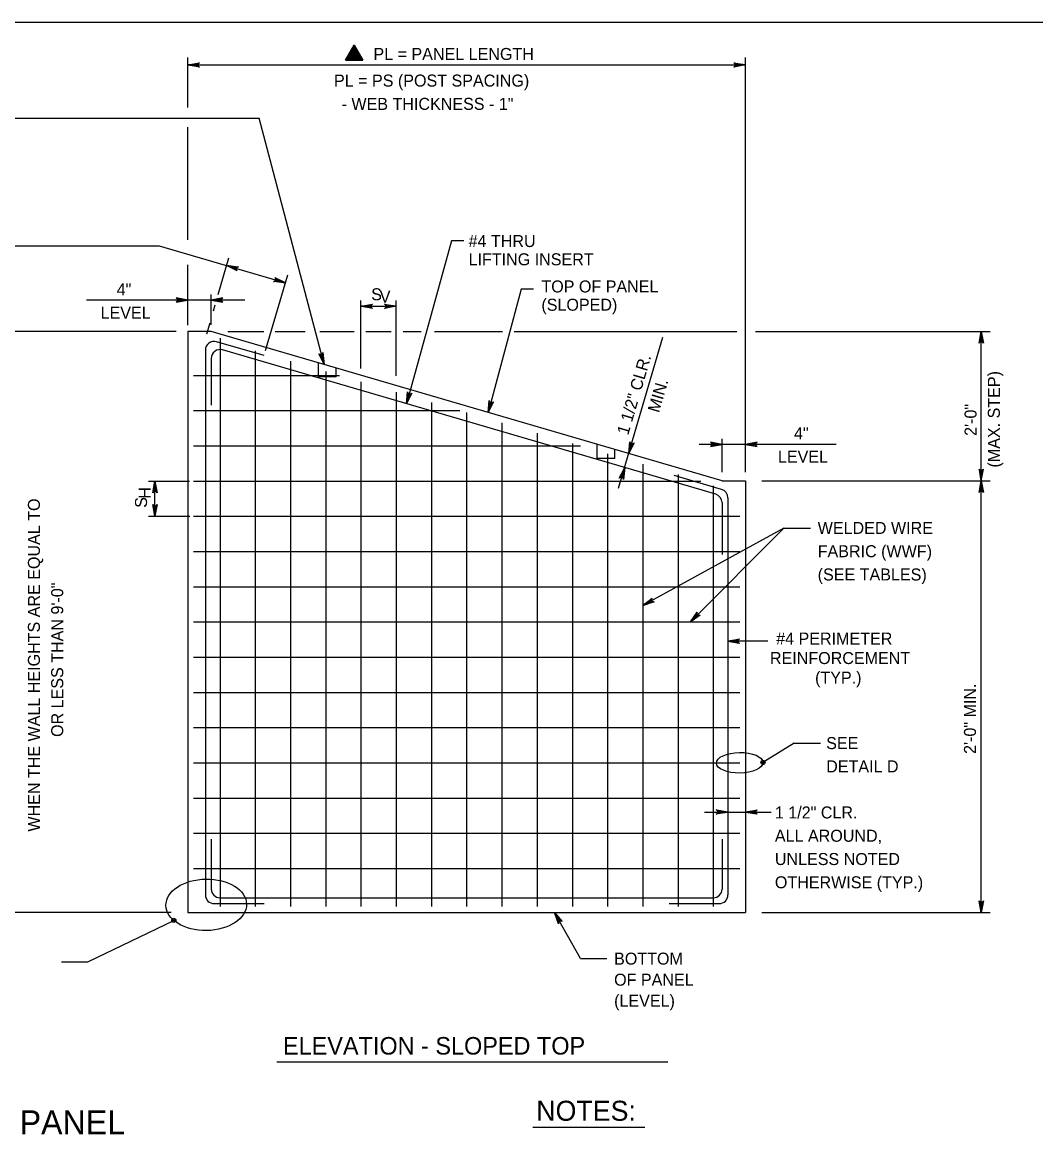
# Model space of a CAD drawing. Extents: x 3761 to 5458, y -616 to 1166.
# Drawn here: x 4072.9 to 4331.8, y -321.6 to -37.3 of the extents above; entities that cross this region are included whole.
import ezdxf

# ---------------------------------------------------------------- set-up
doc = ezdxf.new("R2010")
doc.units = 0
doc.layers.add('1', color=7, linetype='Continuous')
doc.layers.add('2', color=7, linetype='Continuous')

msp = doc.modelspace()

# ---------------------------------------------------------------- linework, layer by layer
at = {"layer": '1'}
for p, q in [((4115.21, -59.07), (4115.21, -46.32)), ((4115.21, -48.22), (4257.71, -48.22)), ((4157.71, -45.74), (4157.71, -45.74)), ((4257.71, -152.33), (4257.71, -46.32)), ((3958.96, -61.84), (4133.46, -61.84)), ((4150.03, -124.76), (4133.46, -61.84)), ((4115.21, -92.92), (4115.21, -64.09)), ((4182.57, -93.18), (4171.13, -134.83)), ((4185.7, -93.18), (4182.57, -93.18)), ((3961.02, -94.44), (4107.86, -94.44)), ((4107.86, -94.44), (4140.16, -103.89)), ((4115.21, -114.74), (4115.21, -99.31)), ((4122.99, -106.92), (4125.74, -97.51)), ((4135.09, -121.22), (4140.74, -101.9)), ((4121.21, -114.61), (4121.21, -106.91)), ((4200.4, -105.5), (4191.97, -137.02)), ((4203.54, -105.5), (4200.4, -105.5)), ((4129.81, -108.31), (4089.32, -108.31)), ((4121.78, -111.04), (4122.22, -109.54)), ((4159.46, -125.78), (4159.46, -108.43)), ((4159.46, -109.9), (4168.46, -109.9)), ((4168.46, -127.71), (4168.46, -108.43)), ((4112.25, -116.32), (3985.19, -116.32)), ((4115.21, -116.32), (4115.21, -264.82)), ((4121.21, -116.32), (4115.21, -116.32)), ((4120.06, -116.92), (4120.89, -114.09)), ((4251.71, -154.5), (4121.21, -116.32)), ((4125.45, -116.32), (4134.66, -116.32)), ((4137.51, -116.32), (4145.24, -116.32)), ((4148.92, -116.32), (4157.7, -116.32)), ((4160.74, -116.32), (4167.17, -116.32)), ((4170.22, -116.32), (4174.81, -116.32)), ((4178.21, -116.32), (4195.63, -116.32)), ((4198.61, -116.32), (4255.48, -116.32)), ((4260.22, -116.32), (4320.16, -116.32)), ((4317.91, -264.82), (4317.91, -116.32)), ((4134.71, -122.51), (4122.58, -118.96)), ((4123.46, -118.08), (4123.46, -263.33)), ((4225.29, -156.39), (4236.59, -117.76)), ((4119.71, -121.11), (4119.71, -260.32)), ((4250.1, -157.93), (4124.08, -121.06)), ((4132.46, -121.28), (4132.46, -263.33)), ((4121.21, -123.21), (4121.21, -135.19)), ((4141.46, -123.92), (4141.46, -263.33)), ((4148.59, -127.97), (4148.59, -124.33)), ((4116.71, -127.57), (4153.97, -127.57)), ((4150.46, -126.55), (4150.46, -263.33)), ((4153.09, -127.97), (4153.09, -125.65)), ((4153.09, -127.97), (4148.59, -127.97)), ((4159.46, -129.18), (4159.46, -263.33)), ((4168.46, -131.81), (4168.46, -263.33)), ((4177.46, -134.45), (4177.46, -263.33)), ((4116.71, -136.57), (4184.74, -136.57)), ((4186.46, -137.08), (4186.46, -263.33)), ((4195.46, -139.71), (4195.46, -263.33)), ((4204.46, -142.34), (4204.46, -263.33)), ((4213.46, -144.98), (4213.46, -263.33)), ((4251.71, -152.33), (4251.71, -143.8)), ((4116.71, -145.57), (4215.51, -145.57)), ((4219.84, -148.81), (4219.84, -145.17)), ((4222.46, -147.61), (4222.46, -263.33)), ((4224.34, -148.81), (4224.34, -146.49)), ((4280.84, -145.21), (4245.83, -145.21)), ((4224.34, -148.81), (4219.84, -148.81)), ((4231.46, -150.24), (4231.46, -263.33)), ((4251.6, -156.7), (4239.47, -153.15)), ((4240.46, -152.87), (4240.46, -263.33)), ((4105.18, -154.57), (4115.62, -154.57)), ((4106.82, -163.57), (4106.82, -154.57)), ((4116.71, -154.57), (4246.28, -154.57)), ((4249.46, -155.75), (4249.46, -263.33)), ((4251.71, -154.5), (4257.71, -154.5)), ((4257.71, -154.5), (4257.71, -264.82)), ((4261.91, -154.5), (4320.16, -154.5)), ((4253.21, -158.85), (4253.21, -260.32)), ((4251.71, -160.08), (4251.71, -173.36)), ((4105.18, -163.57), (4115.7, -163.57)), ((4116.71, -163.57), (4256.21, -163.57)), ((4267.53, -166.62), (4231.46, -186.38)), ((4267.53, -166.62), (4243.61, -190.57)), ((4267.53, -166.62), (4274.26, -166.62)), ((4116.71, -172.57), (4256.21, -172.57)), ((4116.71, -181.57), (4256.21, -181.57)), ((4116.71, -190.57), (4256.21, -190.57)), ((4263.39, -195.48), (4253.21, -195.48)), ((4116.71, -199.57), (4256.21, -199.57)), ((4116.71, -208.57), (4256.21, -208.57)), ((4116.71, -217.57), (4256.21, -217.57)), ((4270.13, -221.56), (4262.15, -226.48)), ((4270.13, -221.56), (4276.87, -221.56)), ((4116.71, -226.57), (4256.21, -226.57)), ((4116.71, -235.57), (4256.21, -235.57)), ((4247.19, -239.15), (4264.24, -239.15)), ((4116.71, -244.57), (4256.21, -244.57)), ((4121.21, -246.08), (4121.21, -258.83)), ((4251.71, -246.08), (4251.71, -258.83)), ((4116.71, -253.57), (4256.21, -253.57)), ((4123.46, -261.08), (4249.46, -261.08)), ((4121.96, -262.57), (4134.71, -262.57)), ((4238.21, -262.57), (4250.96, -262.57)), ((4110.98, -264.82), (3986.76, -264.82)), ((4089.65, -277.4), (4111.63, -266.84)), ((4115.21, -264.82), (4257.71, -264.82)), ((4215.52, -276.61), (4208.91, -264.82)), ((4261.91, -264.82), (4320.16, -264.82)), ((4082.92, -277.4), (4089.65, -277.4)), ((4215.52, -276.61), (4222.25, -276.61)), ((4137.92, -302.99), (4237.83, -302.99)), ((4203.39, -319.69), (4231.96, -319.69))]:
    msp.add_line(p, q, dxfattribs=at)
for points in [[(4155.48, -47.03), (4159.94, -47.03), (4157.71, -43.17), (4155.48, -47.03)], [(4155.48, -47.03), (4157.71, -43.17), (4159.94, -47.03), (4155.48, -47.03), (4157.7, -43.28), (4159.87, -46.98), (4155.56, -46.99), (4157.71, -43.39), (4159.78, -46.92), (4155.67, -46.94), (4157.72, -43.51), (4159.68, -46.85), (4155.77, -46.88), (4157.71, -43.62), (4159.58, -46.8), (4155.88, -46.81), (4157.72, -43.76), (4159.47, -46.75), (4156, -46.75), (4157.71, -43.9), (4159.37, -46.68), (4156.1, -46.69), (4157.71, -44.03), (4159.26, -46.61), (4156.21, -46.62), (4157.71, -44.16), (4159.14, -46.54), (4156.31, -46.56), (4157.72, -44.28), (4159, -46.48), (4156.43, -46.5), (4157.72, -44.41), (4158.87, -46.4), (4156.55, -46.44), (4157.72, -44.56), (4158.75, -46.32), (4156.66, -46.37), (4157.72, -44.69), (4158.63, -46.25), (4156.8, -46.3), (4157.72, -44.82), (4158.52, -46.19), (4156.93, -46.24), (4157.72, -44.97), (4158.39, -46.12), (4157.07, -46.17), (4157.72, -45.1), (4158.26, -46.04), (4157.17, -46.11), (4157.71, -45.23), (4158.13, -45.97), (4157.3, -46.05), (4157.71, -45.36), (4158.03, -45.93), (4157.4, -45.99), (4157.71, -45.48), (4157.93, -45.87), (4157.51, -45.93), (4157.72, -45.61), (4157.84, -45.82), (4157.62, -45.85), (4157.71, -45.75), (4159.93, -47.02), (4157.71, -45.75), (4157.71, -43.19), (4157.72, -45.76), (4155.48, -47.02)], [(4115.21, -48.22), (4118.19, -47.66), (4117.96, -47.82), (4117.84, -48.02), (4117.81, -48.22), (4117.84, -48.42), (4117.96, -48.62), (4118.19, -48.78), (4115.21, -48.22), (4117.96, -48.62), (4117.84, -48.42), (4115.21, -48.22), (4117.81, -48.22), (4117.84, -48.02), (4115.21, -48.22), (4117.96, -47.82)], [(4257.71, -48.22), (4254.73, -48.78), (4254.96, -48.62), (4255.08, -48.42), (4255.11, -48.22), (4255.08, -48.02), (4254.96, -47.82), (4254.73, -47.66), (4257.71, -48.22), (4254.96, -47.82), (4255.08, -48.02), (4257.71, -48.22), (4255.11, -48.22), (4255.08, -48.42), (4257.71, -48.22), (4254.96, -48.62)], [(4125.16, -99.5), (4128.18, -99.8), (4128.04, -99.84), (4127.91, -99.89), (4127.83, -99.97), (4127.74, -100.05), (4127.7, -100.14), (4127.65, -100.23), (4127.64, -100.33), (4127.63, -100.43), (4127.66, -100.54), (4127.69, -100.66), (4127.77, -100.76), (4127.86, -100.87), (4125.16, -99.5), (4127.77, -100.76), (4127.69, -100.66), (4125.16, -99.5), (4127.66, -100.54), (4127.63, -100.43), (4125.16, -99.5), (4127.64, -100.33), (4127.65, -100.23), (4125.16, -99.5), (4127.7, -100.14), (4127.74, -100.05), (4125.16, -99.5), (4127.83, -99.97), (4127.91, -99.89), (4125.16, -99.5), (4128.04, -99.84)], [(4140.16, -103.89), (4137.14, -103.59), (4137.27, -103.54), (4137.4, -103.5), (4137.49, -103.42), (4137.57, -103.34), (4137.62, -103.25), (4137.66, -103.16), (4137.67, -103.06), (4137.68, -102.96), (4137.66, -102.84), (4137.63, -102.73), (4137.54, -102.62), (4137.45, -102.51), (4140.16, -103.89), (4137.54, -102.62), (4137.63, -102.73), (4140.16, -103.89), (4137.66, -102.84), (4137.68, -102.96), (4140.16, -103.89), (4137.67, -103.06), (4137.66, -103.16), (4140.16, -103.89), (4137.62, -103.25), (4137.57, -103.34), (4140.16, -103.89), (4137.49, -103.42), (4137.4, -103.5), (4140.16, -103.89), (4137.27, -103.54)], [(4115.21, -108.31), (4112.23, -107.75), (4112.46, -107.91), (4112.58, -108.11), (4112.61, -108.31), (4112.58, -108.51), (4112.46, -108.71), (4112.23, -108.87), (4115.21, -108.31), (4112.46, -108.71), (4112.58, -108.51), (4115.21, -108.31), (4112.61, -108.31), (4112.58, -108.11), (4115.21, -108.31), (4112.46, -107.91)], [(4121.21, -108.31), (4124.19, -108.87), (4123.96, -108.71), (4123.84, -108.51), (4123.81, -108.31), (4123.84, -108.11), (4123.96, -107.91), (4124.19, -107.75), (4121.21, -108.31), (4123.96, -107.91), (4123.84, -108.11), (4121.21, -108.31), (4123.81, -108.31), (4123.84, -108.51), (4121.21, -108.31), (4123.96, -108.71)], [(4159.46, -109.9), (4162.44, -109.34), (4162.21, -109.5), (4162.09, -109.7), (4162.06, -109.9), (4162.09, -110.1), (4162.21, -110.3), (4162.44, -110.46), (4159.46, -109.9), (4162.21, -110.3), (4162.09, -110.1), (4159.46, -109.9), (4162.06, -109.9), (4162.09, -109.7), (4159.46, -109.9), (4162.21, -109.5)], [(4168.46, -109.9), (4165.48, -110.46), (4165.71, -110.3), (4165.83, -110.1), (4165.86, -109.9), (4165.83, -109.7), (4165.71, -109.5), (4165.48, -109.34), (4168.46, -109.9), (4165.71, -109.5), (4165.83, -109.7), (4168.46, -109.9), (4165.86, -109.9), (4165.83, -110.1), (4168.46, -109.9), (4165.71, -110.3)], [(4317.91, -116.32), (4318.47, -119.31), (4318.31, -119.08), (4318.11, -118.96), (4317.91, -118.92), (4317.71, -118.96), (4317.51, -119.08), (4317.36, -119.31), (4317.91, -116.32), (4317.51, -119.08), (4317.71, -118.96), (4317.91, -116.32), (4317.91, -118.92), (4318.11, -118.96), (4317.91, -116.32), (4318.31, -119.08)], [(4150.03, -124.76), (4148.67, -122.05), (4148.78, -122.14), (4148.88, -122.22), (4149, -122.25), (4149.11, -122.28), (4149.21, -122.27), (4149.31, -122.26), (4149.4, -122.21), (4149.49, -122.17), (4149.57, -122.09), (4149.65, -122), (4149.7, -121.87), (4149.74, -121.74), (4150.03, -124.76), (4149.7, -121.87), (4149.65, -122), (4150.03, -124.76), (4149.57, -122.09), (4149.49, -122.17), (4150.03, -124.76), (4149.4, -122.21), (4149.31, -122.26), (4150.03, -124.76), (4149.21, -122.27), (4149.11, -122.28), (4150.03, -124.76), (4149, -122.25), (4148.88, -122.22), (4150.03, -124.76), (4148.78, -122.14)], [(4171.13, -134.83), (4171.38, -131.8), (4171.47, -132.07), (4171.63, -132.23), (4171.82, -132.32), (4172.02, -132.34), (4172.24, -132.28), (4172.46, -132.1), (4171.13, -134.83), (4172.24, -132.28), (4172.02, -132.34), (4171.13, -134.83), (4171.82, -132.32), (4171.63, -132.23), (4171.13, -134.83), (4171.47, -132.07)], [(4191.97, -137.02), (4192.2, -134), (4192.25, -134.13), (4192.29, -134.26), (4192.37, -134.34), (4192.46, -134.43), (4192.55, -134.47), (4192.64, -134.51), (4192.74, -134.52), (4192.84, -134.53), (4192.95, -134.5), (4193.07, -134.47), (4193.17, -134.38), (4193.28, -134.29), (4191.97, -137.02), (4193.17, -134.38), (4193.07, -134.47), (4191.97, -137.02), (4192.95, -134.5), (4192.84, -134.53), (4191.97, -137.02), (4192.74, -134.52), (4192.64, -134.51), (4191.97, -137.02), (4192.55, -134.47), (4192.46, -134.43), (4191.97, -137.02), (4192.37, -134.34), (4192.29, -134.26), (4191.97, -137.02), (4192.25, -134.13)], [(4227.88, -147.53), (4228.18, -144.51), (4228.27, -144.77), (4228.43, -144.94), (4228.61, -145.03), (4228.81, -145.05), (4229.04, -145), (4229.25, -144.82), (4227.88, -147.53), (4229.04, -145), (4228.81, -145.05), (4227.88, -147.53), (4228.61, -145.03), (4228.43, -144.94), (4227.88, -147.53), (4228.27, -144.77)], [(4251.71, -145.21), (4248.73, -144.65), (4248.96, -144.81), (4249.08, -145.01), (4249.11, -145.21), (4249.08, -145.41), (4248.96, -145.61), (4248.73, -145.77), (4251.71, -145.21), (4248.96, -145.61), (4249.08, -145.41), (4251.71, -145.21), (4249.11, -145.21), (4249.08, -145.01), (4251.71, -145.21), (4248.96, -144.81)], [(4257.71, -145.21), (4260.69, -145.77), (4260.46, -145.61), (4260.34, -145.41), (4260.31, -145.21), (4260.34, -145.01), (4260.46, -144.81), (4260.69, -144.65), (4257.71, -145.21), (4260.46, -144.81), (4260.34, -145.01), (4257.71, -145.21), (4260.31, -145.21), (4260.34, -145.41), (4257.71, -145.21), (4260.46, -145.61)], [(4226.83, -151.12), (4226.53, -154.14), (4226.44, -153.87), (4226.28, -153.7), (4226.1, -153.62), (4225.9, -153.59), (4225.67, -153.65), (4225.45, -153.83), (4226.83, -151.12), (4225.67, -153.65), (4225.9, -153.59), (4226.83, -151.12), (4226.1, -153.62), (4226.28, -153.7), (4226.83, -151.12), (4226.44, -153.87)], [(4317.91, -154.5), (4318.47, -151.51), (4318.31, -151.74), (4318.11, -151.86), (4317.91, -151.9), (4317.71, -151.86), (4317.51, -151.74), (4317.36, -151.51), (4317.91, -154.5), (4317.51, -151.74), (4317.71, -151.86), (4317.91, -154.5), (4317.91, -151.9), (4318.11, -151.86), (4317.91, -154.5), (4318.31, -151.74)], [(4106.82, -154.57), (4107.38, -157.56), (4107.22, -157.33), (4107.02, -157.21), (4106.82, -157.17), (4106.62, -157.21), (4106.42, -157.33), (4106.26, -157.56), (4106.82, -154.57), (4106.42, -157.33), (4106.62, -157.21), (4106.82, -154.57), (4106.82, -157.17), (4107.02, -157.21), (4106.82, -154.57), (4107.22, -157.33)], [(4317.91, -154.5), (4318.47, -157.48), (4318.31, -157.25), (4318.11, -157.13), (4317.91, -157.1), (4317.71, -157.13), (4317.51, -157.25), (4317.36, -157.48), (4317.91, -154.5), (4317.51, -157.25), (4317.71, -157.13), (4317.91, -154.5), (4317.91, -157.1), (4318.11, -157.13), (4317.91, -154.5), (4318.31, -157.25)], [(4106.82, -163.57), (4106.26, -160.59), (4106.42, -160.82), (4106.62, -160.94), (4106.82, -160.97), (4107.02, -160.94), (4107.22, -160.82), (4107.38, -160.59), (4106.82, -163.57), (4107.22, -160.82), (4107.02, -160.94), (4106.82, -163.57), (4106.82, -160.97), (4106.62, -160.94), (4106.82, -163.57), (4106.42, -160.82)], [(4106.82, -163.57), (4106.26, -160.59), (4106.42, -160.82), (4106.62, -160.94), (4106.82, -160.97), (4107.02, -160.94), (4107.22, -160.82), (4107.38, -160.59), (4106.82, -163.57), (4107.22, -160.82), (4107.02, -160.94), (4106.82, -163.57), (4106.82, -160.97), (4106.62, -160.94), (4106.82, -163.57), (4106.42, -160.82)], [(4231.46, -186.38), (4233.81, -184.46), (4233.74, -184.59), (4233.68, -184.71), (4233.68, -184.83), (4233.67, -184.94), (4233.71, -185.04), (4233.74, -185.13), (4233.8, -185.21), (4233.87, -185.29), (4233.97, -185.35), (4234.07, -185.41), (4234.2, -185.43), (4234.34, -185.44), (4231.46, -186.38), (4234.2, -185.43), (4234.07, -185.41), (4231.46, -186.38), (4233.97, -185.35), (4233.87, -185.29), (4231.46, -186.38), (4233.8, -185.21), (4233.74, -185.13), (4231.46, -186.38), (4233.71, -185.04), (4233.67, -184.94), (4231.46, -186.38), (4233.68, -184.83), (4233.68, -184.71), (4231.46, -186.38), (4233.74, -184.59)], [(4243.61, -190.57), (4245.32, -188.07), (4245.29, -188.21), (4245.27, -188.34), (4245.3, -188.46), (4245.33, -188.57), (4245.39, -188.65), (4245.44, -188.73), (4245.53, -188.79), (4245.61, -188.85), (4245.72, -188.88), (4245.84, -188.91), (4245.97, -188.88), (4246.11, -188.86), (4243.61, -190.57), (4245.97, -188.88), (4245.84, -188.91), (4243.61, -190.57), (4245.72, -188.88), (4245.61, -188.85), (4243.61, -190.57), (4245.53, -188.79), (4245.44, -188.73), (4243.61, -190.57), (4245.39, -188.65), (4245.33, -188.57), (4243.61, -190.57), (4245.3, -188.46), (4245.27, -188.34), (4243.61, -190.57), (4245.29, -188.21)], [(4253.21, -195.48), (4256.19, -194.92), (4256.08, -195), (4255.96, -195.08), (4255.9, -195.18), (4255.85, -195.28), (4255.83, -195.38), (4255.81, -195.48), (4255.83, -195.58), (4255.85, -195.68), (4255.9, -195.78), (4255.96, -195.88), (4256.08, -195.96), (4256.19, -196.04), (4253.21, -195.48), (4256.08, -195.96), (4255.96, -195.88), (4253.21, -195.48), (4255.9, -195.78), (4255.85, -195.68), (4253.21, -195.48), (4255.83, -195.58), (4255.81, -195.48), (4253.21, -195.48), (4255.83, -195.38), (4255.85, -195.28), (4253.21, -195.48), (4255.9, -195.18), (4255.96, -195.08), (4253.21, -195.48), (4256.08, -195)], [(4253.21, -239.15), (4250.23, -239.71), (4250.34, -239.63), (4250.46, -239.55), (4250.52, -239.45), (4250.58, -239.35), (4250.59, -239.25), (4250.61, -239.15), (4250.59, -239.05), (4250.58, -238.95), (4250.52, -238.85), (4250.46, -238.75), (4250.34, -238.67), (4250.23, -238.59), (4253.21, -239.15), (4250.34, -238.67), (4250.46, -238.75), (4253.21, -239.15), (4250.52, -238.85), (4250.58, -238.95), (4253.21, -239.15), (4250.59, -239.05), (4250.61, -239.15), (4253.21, -239.15), (4250.59, -239.25), (4250.58, -239.35), (4253.21, -239.15), (4250.52, -239.45), (4250.46, -239.55), (4253.21, -239.15), (4250.34, -239.63)], [(4257.71, -239.15), (4260.69, -238.59), (4260.58, -238.67), (4260.46, -238.75), (4260.4, -238.85), (4260.35, -238.95), (4260.33, -239.05), (4260.31, -239.15), (4260.33, -239.25), (4260.35, -239.35), (4260.4, -239.45), (4260.46, -239.55), (4260.58, -239.63), (4260.69, -239.71), (4257.71, -239.15), (4260.58, -239.63), (4260.46, -239.55), (4257.71, -239.15), (4260.4, -239.45), (4260.35, -239.35), (4257.71, -239.15), (4260.33, -239.25), (4260.31, -239.15), (4257.71, -239.15), (4260.33, -239.05), (4260.35, -238.95), (4257.71, -239.15), (4260.4, -238.85), (4260.46, -238.75), (4257.71, -239.15), (4260.58, -238.67)], [(4317.91, -264.82), (4317.36, -261.84), (4317.43, -261.96), (4317.51, -262.07), (4317.61, -262.13), (4317.71, -262.19), (4317.81, -262.21), (4317.91, -262.22), (4318.01, -262.21), (4318.11, -262.19), (4318.21, -262.13), (4318.31, -262.07), (4318.39, -261.96), (4318.47, -261.84), (4317.91, -264.82), (4318.39, -261.96), (4318.31, -262.07), (4317.91, -264.82), (4318.21, -262.13), (4318.11, -262.19), (4317.91, -264.82), (4318.01, -262.21), (4317.91, -262.22), (4317.91, -264.82), (4317.81, -262.21), (4317.71, -262.19), (4317.91, -264.82), (4317.61, -262.13), (4317.51, -262.07), (4317.91, -264.82), (4317.43, -261.96)], [(4208.91, -264.82), (4210.86, -267.15), (4210.61, -267.03), (4210.37, -267.02), (4210.18, -267.09), (4210.03, -267.22), (4209.91, -267.42), (4209.88, -267.7), (4208.91, -264.82), (4209.91, -267.42), (4210.03, -267.22), (4208.91, -264.82), (4210.18, -267.09), (4210.37, -267.02), (4208.91, -264.82), (4210.61, -267.03)]]:
    msp.add_lwpolyline(points, dxfattribs=at)
for centre, radius in [((4262.15, -226.48), 0.533), ((4262.15, -226.48), 0.267), ((4111.63, -266.84), 0.533), ((4111.63, -266.84), 0.267)]:
    msp.add_circle(centre, radius, dxfattribs=at)
for centre, radius, start, end in [((4121.95, -121.11), 2.24, 73.6954, 180), ((4123.45, -123.21), 2.24, 73.6954, 180), ((4249.47, -160.08), 2.24, 0, 73.6954), ((4250.97, -158.85), 2.24, 0, 73.6954), ((4121.96, -260.32), 2.25, 180, 270), ((4123.46, -258.83), 2.25, 180, 270), ((4249.46, -258.83), 2.25, 270, 360), ((4250.96, -260.32), 2.25, 270, 0)]:
    msp.add_arc(centre, radius, start, end, dxfattribs=at)
for centre, major_axis, ratio in [((4256.21, -226.57), (-5.94, -0.09), 0.443512), ((4119.93, -262.86), (-10.3, -0.16), 0.638969)]:
    msp.add_ellipse(centre, major_axis=major_axis, ratio=ratio, dxfattribs=at)
at = {"layer": '2'}
msp.add_line((3801.34, -37.31), (4587.34, -37.31), dxfattribs=at)

# ---------------------------------------------------------------- texts
at = {"layer": '1'}
for s, height, p in [('PL = PANEL LENGTH', 3.072, (4162.65, -46.95)), ('PL = PS (POST SPACING)', 3.072, (4152.57, -53.75)), ('- WEB THICKNESS - 1"', 3.072, (4154.51, -59.7)), ('#4 THRU ', 3.072, (4186.95, -94.76)), ('LIFTING INSERT', 3.0721, (4186.95, -99.43)), ('4"', 3.072, (4097.04, -107.14)), ('TOP OF PANEL', 3.072, (4205.55, -106.37)), ('S', 3.07, (4162.07, -108.37)), ('V', 3.07, (4164.25, -108.99)), ('(SLOPED)', 3.072, (4205.55, -111.04)), ('LEVEL', 3.072, (4092.94, -113.09)), ('4"', 3.072, (4270.08, -143.91)), ('LEVEL', 3.072, (4265.98, -149.86)), ('WELDED WIRE', 3.072, (4276.14, -168.08)), ('FABRIC (WWF)', 3.072, (4276.14, -174.03)), ('(SEE TABLES)', 3.072, (4276.14, -179.98)), ('#4 PERIMETER', 3.072, (4265.54, -196.35)), ('REINFORCEMENT', 3.072, (4263.94, -201.34)), ('(TYP.)', 3.072, (4275.47, -206.33)), ('SEE', 3.072, (4278.31, -223.07)), ('DETAIL D', 3.072, (4278.31, -229.02)), ('1 1/2" CLR.', 3.072, (4265.2, -240.8)), ('ALL AROUND,', 3.072, (4265.2, -246.75)), ('UNLESS NOTED', 3.072, (4265.2, -252.7)), ('OTHERWISE (TYP.)', 3.072, (4265.2, -258.65)), ('BOTTOM', 3.072, (4224.13, -278.16)), ('OF PANEL', 3.072, (4224.13, -283.54)), ('(LEVEL)', 3.072, (4224.13, -288.91)), ('ELEVATION - SLOPED TOP', 4.4774, (4139.54, -301.14)), ('PRECAST CONCRETE PANEL', 6.144, (3982.78, -321.54)), ('NOTES:', 5.117, (4204.23, -318.06))]:
    msp.add_text(s, height=height, dxfattribs=at).set_placement(p)
for s, height, rotation, p in [('1 1/2" CLR.', 3.072, 73.6955, (4227.72, -142.97)), ('(MAX. STEP)', 3.072, 90, (4322.68, -151.11)), ('MIN.', 3.072, 73.6955, (4235.59, -137.27)), ('2\'-0"', 3.072, 90, (4316.73, -143.03)), ('WHEN THE WALL HEIGHTS ARE EQUAL TO', 3.072, 90, (4077.44, -244.16)), ('S', 3.07, 90, (4104.8, -161.4)), ('H', 3.07, 90, (4105.77, -159.07)), ('OR LESS THAN 9\'-0"', 3.072, 90, (4083.39, -219.96)), ('2\'-0" MIN.', 3.072, 90, (4316.58, -224.31))]:
    msp.add_text(s, height=height, rotation=rotation, dxfattribs=at).set_placement(p)

doc.saveas('drawing.dxf')
